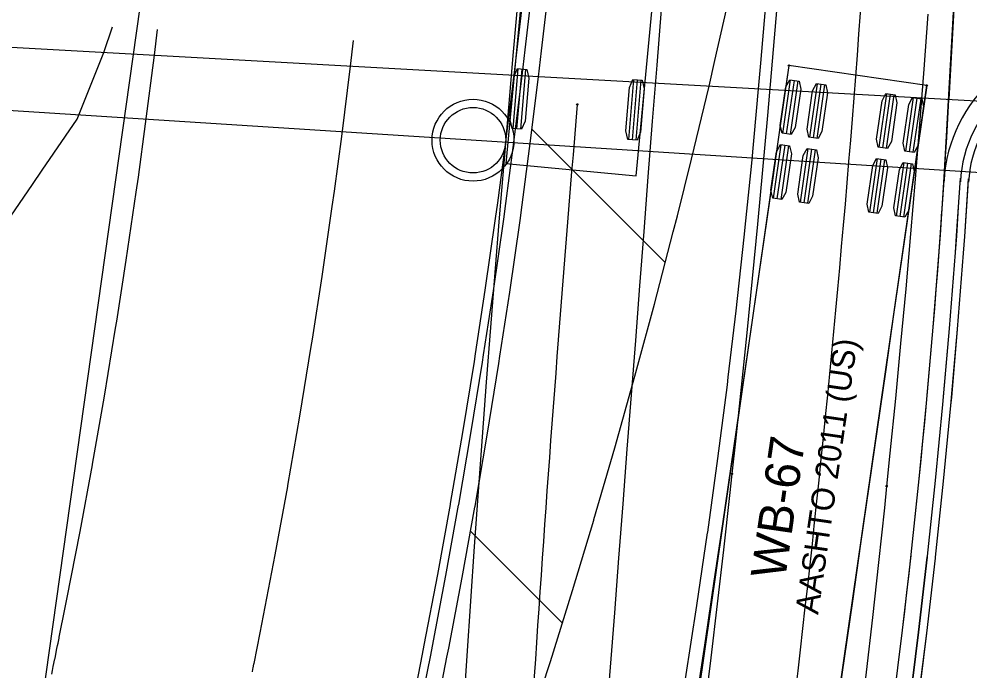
# Model space of a CAD drawing. Extents: x -70 to 701944, y -4 to 666871.
# Drawn here: x 664327.1 to 664385.1, y 657047.3 to 657087.1 of the extents above; entities that cross this region are included whole.
import ezdxf

# ---------------------------------------------------------------- set-up
doc = ezdxf.new("R2010")
doc.units = 0
for name, color, linetype in [('R_Detour', 7, 'Continuous'), ('R_Horz Alg', 7, 'Continuous'), ('R_Horz Alg Annot', 7, 'Continuous'), ('R_No Plot', 7, 'Continuous'), ('R_Proposed Const Limits', 7, 'Continuous'), ('R_Proposed Road', 7, 'Continuous'), ('R_Striping', 7, 'Continuous'), ('R_Water', 7, 'Continuous'), ('T_Vehicle Path Lt Major', 7, 'Continuous'), ('T_Vehicle Path Lt Minor', 7, 'Continuous'), ('T_Vehicle Path Rt', 7, 'Continuous')]:
    doc.layers.add(name, color=color, linetype=linetype)

msp = doc.modelspace()

# ---------------------------------------------------------------- linework, layer by layer
at = {"layer": 'R_Detour'}
msp.add_line((664655.681, 657060.389), (664209.634, 657089.014), dxfattribs=at)
at = {"layer": 'R_Horz Alg'}
msp.add_arc((663872.762, 657110.632), 520.871, 348.49417, 356.81395, dxfattribs=at)
at = {"layer": 'R_Horz Alg Annot'}
msp.add_lwpolyline([(664392.828, 657081.683), (664241.653, 657090.098)], dxfattribs=at)
at = {"layer": 'R_No Plot'}
msp.add_line((664390.623, 657204.009), (664383.842, 657082.184), dxfattribs=at)
msp.add_lwpolyline([(664328.065, 657042.491), (664341.279, 657136.216), (664395.695, 657133.187), (664392.683, 657079.188), (664387.896, 657033.536)], close=True, dxfattribs=at)
msp.add_circle((664354.78, 657079.699), 2.5, dxfattribs=at)
msp.add_arc((663872.762, 657110.633), 511.871, 348.49414, 356.81396, dxfattribs=at)
at = {"layer": 'R_Proposed Const Limits'}
msp.add_lwpolyline([(664325.175, 657073.072), (664327.879, 657077.003), (664328.474, 657077.872), (664330.611, 657080.976), (664332.245, 657085.056), (664332.763, 657086.613)], dxfattribs=at)
at = {"layer": 'R_Proposed Road'}
for points in [[(664351.322, 657046.435), (664351.698, 657048.329), (664351.805, 657048.875), (664352.627, 657053.192), (664353.402, 657057.469), (664353.41, 657057.518), (664354.155, 657061.853), (664354.86, 657066.198), (664354.931, 657066.651), (664355.526, 657070.552), (664356.153, 657074.914), (664356.285, 657075.872), (664356.74, 657079.284), (664357.288, 657083.662), (664357.471, 657085.237), (664357.753, 657087.665)], [(664351.817, 657046.369), (664352.193, 657048.264), (664352.3, 657048.811), (664353.123, 657053.132), (664353.899, 657057.414), (664353.907, 657057.463), (664354.652, 657061.803), (664355.358, 657066.152), (664355.429, 657066.606), (664356.024, 657070.51), (664356.652, 657074.877), (664356.784, 657075.837), (664357.239, 657079.252), (664357.787, 657083.634), (664357.97, 657085.21), (664358.242, 657087.638)], [(664352.808, 657046.236), (664353.185, 657048.135), (664353.292, 657048.683), (664354.116, 657053.013), (664354.893, 657057.304), (664354.901, 657057.353), (664355.647, 657061.702), (664356.354, 657066.061), (664356.425, 657066.515), (664357.021, 657070.428), (664357.649, 657074.803), (664357.781, 657075.765), (664358.237, 657079.187), (664358.786, 657083.578), (664358.968, 657085.154), (664359.25, 657087.582)], [(664329.051, 657047.105), (664329.098, 657047.329), (664329.15, 657047.58), (664329.247, 657048.045), (664329.254, 657048.081), (664329.375, 657048.667), (664329.415, 657048.86), (664329.444, 657049.006), (664329.463, 657049.097), (664329.506, 657049.305), (664329.506, 657049.306), (664329.508, 657049.317), (664329.51, 657049.325), (664329.513, 657049.34), (664329.517, 657049.36), (664329.881, 657051.167), (664329.985, 657051.688), (664330.783, 657055.806), (664331.535, 657059.887), (664331.543, 657059.934), (664332.267, 657064.071), (664332.953, 657068.217), (664333.022, 657068.649), (664333.602, 657072.372), (664334.213, 657076.535), (664334.342, 657077.45), (664334.786, 657080.706), (664335.322, 657084.884), (664335.505, 657086.46)], [(664341.306, 657047.252), (664341.337, 657047.401), (664341.356, 657047.494), (664341.399, 657047.709), (664341.399, 657047.71), (664341.401, 657047.72), (664341.403, 657047.728), (664341.406, 657047.744), (664341.41, 657047.765), (664341.781, 657049.619), (664341.887, 657050.154), (664342.698, 657054.38), (664343.462, 657058.568), (664343.471, 657058.616), (664344.206, 657062.862), (664344.902, 657067.116), (664344.973, 657067.559), (664345.56, 657071.379), (664346.18, 657075.651), (664346.311, 657076.59), (664346.761, 657079.93), (664347.303, 657084.217), (664347.486, 657085.793)], [(664380.432, 657045.185), (664381.005, 657049.795), (664381.53, 657054.357), (664381.536, 657054.41), (664382.025, 657059.029), (664382.473, 657063.653), (664382.517, 657064.135), (664382.878, 657068.281), (664383.241, 657072.912), (664383.315, 657073.929), (664383.556, 657077.446)], [(664381.416, 657045.059), (664381.99, 657049.676), (664382.517, 657054.246), (664382.523, 657054.302), (664383.013, 657058.929), (664383.461, 657063.56), (664383.505, 657064.046), (664383.867, 657068.199), (664384.231, 657072.837), (664384.306, 657073.859), (664384.546, 657077.378)], [(664381.909, 657044.996), (664382.483, 657049.617), (664383.01, 657054.19), (664383.016, 657054.249), (664383.507, 657058.879), (664383.955, 657063.513), (664384, 657064.002), (664384.362, 657068.158), (664384.726, 657072.8), (664384.801, 657073.824), (664385.041, 657077.344)], [(664381.919, 657044.993), (664382.494, 657049.616), (664383.021, 657054.192), (664383.027, 657054.245), (664383.518, 657058.878), (664383.966, 657063.515), (664384.011, 657063.998), (664384.373, 657068.157), (664384.737, 657072.802), (664384.812, 657073.822), (664385.024, 657076.924)], [(664380.432, 657045.185), (664381.005, 657049.795), (664381.53, 657054.357), (664381.536, 657054.41), (664382.025, 657059.029), (664382.473, 657063.653), (664382.517, 657064.135), (664382.878, 657068.281), (664383.241, 657072.912), (664383.315, 657073.929), (664383.415, 657075.392)], [(664381.423, 657045.057), (664381.998, 657049.676), (664382.524, 657054.247), (664382.53, 657054.3), (664383.02, 657058.928), (664383.468, 657063.561), (664383.513, 657064.044), (664383.875, 657068.198), (664384.239, 657072.838), (664384.313, 657073.858), (664384.433, 657075.612)]]:
    msp.add_lwpolyline(points, dxfattribs=at)
for radius in [9.001, 8.001, 7.501]:
    msp.add_arc((664392.527, 657076.72), radius, 356.81794, 176.80996, dxfattribs=at)
at = {"layer": 'R_Striping'}
for p, q in [((664358.384, 657080.36), (664366.517, 657072.226)), ((664354.626, 657055.833), (664360.236, 657050.223))]:
    msp.add_line(p, q, dxfattribs=at)
for points in [[(664383.556, 657077.446), (664385.041, 657103.734), (664386.564, 657113.664), (664387.326, 657118.63), (664388.087, 657123.595), (664389.038, 657129.793), (664389.61, 657133.526), (664391.134, 657143.456), (664392.657, 657153.387), (664394.18, 657163.318), (664395.703, 657173.249), (664397.226, 657183.179), (664398.749, 657193.11)], [(664358.121, 657043.578), (664359.333, 657047.335), (664359.507, 657047.882), (664360.854, 657052.207), (664362.148, 657056.501), (664362.163, 657056.551), (664363.433, 657060.913), (664364.664, 657065.295), (664364.79, 657065.752), (664365.856, 657069.694), (664367.009, 657074.112), (664367.257, 657075.084), (664368.122, 657078.547), (664369.195, 657082.999), (664369.552, 657084.565), (664371.805, 657094.455)], [(664367.755, 657046.819), (664368.454, 657051.297), (664369.106, 657055.732), (664369.113, 657055.782), (664369.732, 657060.275), (664370.309, 657064.774), (664370.367, 657065.243), (664370.846, 657069.28), (664371.343, 657073.791), (664371.446, 657074.783), (664371.798, 657078.308), (664372.212, 657082.831), (664372.348, 657084.409), (664373.203, 657094.377)]]:
    msp.add_lwpolyline(points, dxfattribs=at)
at = {"layer": 'R_Water'}
msp.add_circle((664354.78, 657079.699), 2, dxfattribs=at)
at = {"layer": 'T_Vehicle Path Lt Major'}
for points in [[(664373.326, 657087.835), (664373.045, 657084.517), (664372.754, 657081.2), (664372.453, 657077.884), (664372.143, 657074.569), (664371.823, 657071.255), (664371.493, 657067.943), (664371.152, 657064.631), (664370.801, 657061.321), (664370.586, 657059.335)], [(664382.549, 657087.386), (664382.304, 657084.034), (664382.047, 657080.682), (664381.777, 657077.332), (664381.494, 657073.983), (664381.199, 657070.635), (664380.892, 657067.288), (664380.573, 657063.942), (664380.241, 657060.597), (664380.036, 657058.591)], [(664370.586, 657059.335), (664370.44, 657058.012), (664370.069, 657054.704), (664369.687, 657051.398), (664369.295, 657048.093), (664368.892, 657044.79), (664368.478, 657041.488), (664368.054, 657038.187), (664367.619, 657034.888), (664367.174, 657031.59), (664366.717, 657028.294), (664366.25, 657024.999), (664365.772, 657021.707), (664365.283, 657018.42), (664364.784, 657015.135), (664364.274, 657011.851), (664363.963, 657009.882)], [(664380.036, 657058.591), (664379.897, 657057.254), (664379.54, 657053.912), (664379.171, 657050.571), (664378.79, 657047.231), (664378.397, 657043.893), (664377.992, 657040.556), (664377.575, 657037.221), (664377.146, 657033.887), (664376.706, 657030.555), (664376.255, 657027.224), (664375.792, 657023.895), (664375.317, 657020.568), (664374.832, 657017.248), (664374.335, 657013.93), (664373.827, 657010.614), (664373.516, 657008.625)]]:
    msp.add_lwpolyline(points, dxfattribs=at)
for centre in [(664370.586, 657059.335), (664370.586, 657059.335), (664380.036, 657058.591), (664380.036, 657058.591)]:
    msp.add_circle(centre, 0.0417, dxfattribs=at)
msp.add_arc((663455.405, 657154.995), 925.505, 351.947905, 357.106325, dxfattribs=at)
at = {"layer": 'T_Vehicle Path Lt Minor'}
for p, q in [((664374.07, 657084.255), (664366.504, 657031.797)), ((664382.483, 657083.041), (664374.07, 657084.255)), ((664373.704, 657080.115), (664374.175, 657083.381)), ((664373.931, 657080.082), (664374.402, 657083.348)), ((664374.158, 657080.049), (664374.629, 657083.315)), ((664374.917, 657030.584), (664382.483, 657083.041)), ((664375.337, 657079.879), (664375.808, 657083.145)), ((664375.564, 657079.846), (664376.035, 657083.112)), ((664375.791, 657079.814), (664376.262, 657083.08)), ((664379.577, 657079.268), (664380.048, 657082.534)), ((664379.804, 657079.235), (664380.275, 657082.501)), ((664380.03, 657079.202), (664380.501, 657082.468)), ((664381.21, 657079.032), (664381.681, 657082.298)), ((664381.437, 657078.999), (664381.908, 657082.266)), ((664381.664, 657078.967), (664382.135, 657082.233)), ((664373.133, 657076.155), (664373.604, 657079.422)), ((664373.36, 657076.123), (664373.831, 657079.389)), ((664373.587, 657076.09), (664374.058, 657079.356)), ((664374.766, 657075.92), (664375.237, 657079.186)), ((664374.993, 657075.887), (664375.464, 657079.153)), ((664375.22, 657075.855), (664375.691, 657079.121)), ((664379.006, 657075.309), (664379.477, 657078.575)), ((664379.233, 657075.276), (664379.704, 657078.542)), ((664379.459, 657075.243), (664379.931, 657078.509)), ((664380.639, 657075.073), (664381.11, 657078.339)), ((664380.866, 657075.04), (664381.337, 657078.307)), ((664381.093, 657075.008), (664381.564, 657078.274))]:
    msp.add_line(p, q, dxfattribs=at)
for points in [[(664374.07, 657084.255), (664373.565, 657080.758), (664373.061, 657077.26), (664372.556, 657073.763), (664372.05, 657070.266), (664371.543, 657066.77), (664371.034, 657063.273), (664370.523, 657059.777), (664370.009, 657056.281), (664369.492, 657052.786), (664368.972, 657049.291), (664368.449, 657045.797)], [(664382.483, 657083.041), (664381.979, 657079.544), (664381.475, 657076.047), (664380.97, 657072.55), (664380.465, 657069.053), (664379.961, 657065.556), (664379.457, 657062.059), (664378.952, 657058.561), (664378.448, 657055.064), (664377.944, 657051.567), (664377.439, 657048.07), (664376.935, 657044.573)]]:
    msp.add_lwpolyline(points, dxfattribs=at)
for points in [[(664374.214, 657080.041), (664373.648, 657080.123), (664373.543, 657080.604), (664373.882, 657082.956), (664374.119, 657083.389), (664374.685, 657083.307), (664374.79, 657082.825), (664374.451, 657080.474)], [(664375.847, 657079.805), (664375.281, 657079.887), (664375.176, 657080.369), (664375.516, 657082.721), (664375.752, 657083.153), (664376.318, 657083.072), (664376.423, 657082.59), (664376.084, 657080.238)], [(664380.087, 657079.194), (664379.521, 657079.276), (664379.416, 657079.758), (664379.755, 657082.109), (664379.992, 657082.542), (664380.558, 657082.46), (664380.662, 657081.978), (664380.323, 657079.627)], [(664381.72, 657078.959), (664381.154, 657079.04), (664381.049, 657079.522), (664381.388, 657081.874), (664381.625, 657082.306), (664382.191, 657082.225), (664382.295, 657081.743), (664381.956, 657079.391)], [(664373.643, 657076.082), (664373.077, 657076.164), (664372.972, 657076.645), (664373.312, 657078.997), (664373.548, 657079.43), (664374.114, 657079.348), (664374.219, 657078.866), (664373.88, 657076.515)], [(664375.276, 657075.846), (664374.71, 657075.928), (664374.605, 657076.41), (664374.945, 657078.762), (664375.181, 657079.194), (664375.747, 657079.113), (664375.852, 657078.631), (664375.513, 657076.279)], [(664379.516, 657075.235), (664378.95, 657075.317), (664378.845, 657075.799), (664379.184, 657078.15), (664379.421, 657078.583), (664379.987, 657078.501), (664380.091, 657078.019), (664379.752, 657075.668)], [(664381.149, 657074.999), (664380.583, 657075.081), (664380.478, 657075.563), (664380.817, 657077.915), (664381.054, 657078.347), (664381.62, 657078.266), (664381.724, 657077.784), (664381.385, 657075.432)]]:
    msp.add_lwpolyline(points, close=True, dxfattribs=at)
for centre in [(664374.07, 657084.255), (664382.483, 657083.041)]:
    msp.add_circle(centre, 0.0417, dxfattribs=at)
at = {"layer": 'T_Vehicle Path Rt'}
for p, q in [((664358.206, 657093.216), (664356.783, 657078.283)), ((664364.747, 657077.524), (664366.17, 657092.457)), ((664357.235, 657080.409), (664357.544, 657084.063)), ((664357.463, 657080.39), (664357.773, 657084.044)), ((664357.692, 657080.371), (664358.001, 657084.024)), ((664364.287, 657079.747), (664364.597, 657083.401)), ((664364.515, 657079.728), (664364.825, 657083.381)), ((664364.744, 657079.708), (664365.053, 657083.362)), ((664356.783, 657078.283), (664364.747, 657077.524)), ((664364.747, 657077.524), (664364.747, 657077.524))]:
    msp.add_line(p, q, dxfattribs=at)
for points in [[(664357.537, 657088.508), (664357.236, 657085.104), (664356.944, 657081.7), (664356.656, 657078.295), (664356.656, 657078.295), (664356.381, 657074.956), (664356.111, 657071.616), (664355.848, 657068.275), (664355.591, 657064.934), (664355.34, 657061.593), (664355.095, 657058.251), (664354.857, 657054.908), (664354.625, 657051.566), (664354.398, 657048.222), (664354.178, 657044.879), (664353.957, 657041.872)], [(664366.268, 657087.677), (664365.994, 657084.272), (664365.724, 657080.866), (664365.459, 657077.46), (664365.459, 657077.46), (664365.203, 657074.134), (664364.948, 657070.808), (664364.692, 657067.482), (664364.434, 657064.156), (664364.178, 657060.831), (664363.922, 657057.505), (664363.666, 657054.179), (664363.41, 657050.854), (664363.154, 657047.528), (664362.898, 657044.203), (664362.668, 657041.21)]]:
    msp.add_lwpolyline(points, dxfattribs=at)
for points in [[(664357.748, 657080.366), (664357.178, 657080.414), (664357.05, 657080.94), (664357.273, 657083.571), (664357.488, 657084.068), (664358.058, 657084.02), (664358.186, 657083.494), (664357.963, 657080.863)], [(664364.8, 657079.704), (664364.231, 657079.752), (664364.102, 657080.278), (664364.325, 657082.909), (664364.54, 657083.406), (664365.11, 657083.357), (664365.238, 657082.831), (664365.016, 657080.201)]]:
    msp.add_lwpolyline(points, close=True, dxfattribs=at)
msp.add_circle((664361.144, 657081.886), 0.0417, dxfattribs=at)
msp.add_arc((666209.939, 656925.295), 1855.415, 175.158671, 177.192659, dxfattribs=at)

# ---------------------------------------------------------------- texts
at = {"layer": 'T_Vehicle Path Lt Minor'}
for s, height, p in [('AASHTO 2011 (US)', 1.41667, (664375.851, 657050.707)), ('WB-67', 2.125, (664373.834, 657052.849))]:
    msp.add_text(s, height=height, rotation=81.79349, dxfattribs=at).set_placement(p)

doc.saveas('drawing.dxf')
